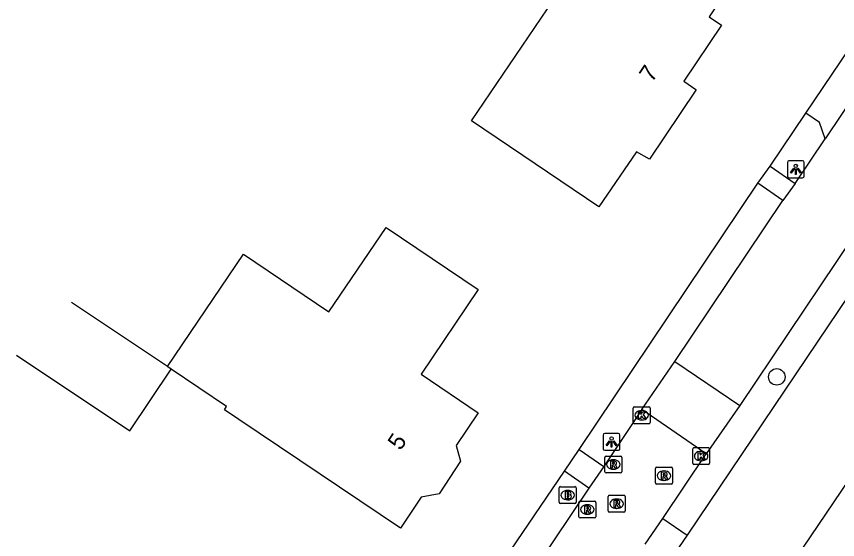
# Model space of a CAD drawing. Extents: x 163863 to 164644, y 379566 to 382155.
# Drawn here: x 164126.18 to 164174.78, y 381800.42 to 381831.4 of the extents above; entities that cross this region are included whole.
import ezdxf

# ---------------------------------------------------------------- set-up
doc = ezdxf.new("R2010")
doc.units = 0
for name, color, linetype in [('IMGEO_Boom', 7, 'Continuous'), ('IMGEO_Brandkraan', 7, 'Continuous'), ('IMGEO_Kolk', 7, 'Continuous'), ('IMGEO_Lichtpunt', 7, 'Continuous'), ('IMGEO_Pand', 7, 'Continuous'), ('IMGEO_Pand_nummerreeks', 7, 'Continuous'), ('IMGEO_Rijbaan_lokaal_open', 7, 'Continuous'), ('IMGEO_Rioolput', 7, 'Continuous'), ('IMGEO_Voetpad_halfverhard', 7, 'Continuous'), ('IMGEO_Voetpad_open', 7, 'Continuous')]:
    doc.layers.add(name, color=color, linetype=linetype)

msp = doc.modelspace()

# ---------------------------------------------------------------- linework, layer by layer
at = {"layer": 'IMGEO_Boom'}
msp.add_circle((164171.182, 381810.055), 0.489, dxfattribs=at)
at = {"layer": 'IMGEO_Brandkraan'}
for p, q in [((164158.31, 381802.628), (164158.31, 381803.48)), ((164158.385, 381803.554), (164159.237, 381803.554)), ((164158.798, 381803.334), (164158.823, 381803.334)), ((164159.311, 381803.48), (164159.311, 381802.628)), ((164159.237, 381802.554), (164158.385, 381802.554)), ((164158.821, 381802.774), (164158.796, 381802.774))]:
    msp.add_line(p, q, dxfattribs=at)
for points in [[(164158.31, 381802.628), (164158.31, 381803.48)], [(164158.385, 381803.554), (164159.237, 381803.554)], [(164159.311, 381803.48), (164159.311, 381802.628)], [(164158.658, 381803.254), (164158.658, 381802.854), (164158.871, 381802.854)], [(164158.889, 381803.254), (164158.658, 381803.254)], [(164158.837, 381803.173), (164158.783, 381803.173), (164158.783, 381803.097)], [(164158.783, 381803.097), (164158.836, 381803.097)], [(164158.845, 381803.021), (164158.783, 381803.021), (164158.783, 381802.94)], [(164158.783, 381802.94), (164158.845, 381802.94)], [(164159.237, 381802.554), (164158.385, 381802.554)]]:
    msp.add_lwpolyline(points, dxfattribs=at)
for centre, radius, start, end in [((164158.387, 381803.478), 0.0765, 91.552, 178.448), ((164158.387, 381803.478), 0.0765, 91.552, 178.448), ((164159.235, 381803.478), 0.0765, 1.552, 88.448), ((164159.235, 381803.478), 0.0765, 1.552, 88.448), ((164158.838, 381803.135), 0.0379, 267.8285, 90.9355), ((164158.846, 381802.98), 0.0404, 269.8759, 90.5077), ((164158.877, 381803.105), 0.251, 268.6676, 293.5347), ((164158.893, 381803.109), 0.145, 59.4692, 91.5367), ((164158.918, 381803.156), 0.0922, 285.5137, 58.1501), ((164158.923, 381802.964), 0.105, 301.3115, 78.989), ((164158.387, 381802.63), 0.0765, 181.552, 268.448), ((164158.387, 381802.63), 0.0765, 181.552, 268.448), ((164159.235, 381802.63), 0.0765, 271.552, 358.448), ((164159.235, 381802.63), 0.0765, 271.552, 358.448)]:
    msp.add_arc(centre, radius, start, end, dxfattribs=at)
for centre, major_axis, ratio, start_param, end_param in [((164158.797, 381803.054), (-0.387, 0.002), 0.722429, 4.712389, 7.853982), ((164158.822, 381803.054), (-0.39, 0.002), 0.717154, 1.570796, 4.712389)]:
    msp.add_ellipse(centre, major_axis=major_axis, ratio=ratio, start_param=start_param, end_param=end_param, dxfattribs=at)
at = {"layer": 'IMGEO_Kolk'}
for p, q in [((164162.687, 381807.358), (164162.687, 381808.21)), ((164162.762, 381808.284), (164163.614, 381808.284)), ((164163.688, 381808.21), (164163.688, 381807.358)), ((164163.175, 381808.064), (164163.2, 381808.064)), ((164163.614, 381807.284), (164162.762, 381807.284)), ((164163.198, 381807.504), (164163.173, 381807.504)), ((164166.206, 381804.939), (164166.206, 381805.791)), ((164166.281, 381805.865), (164167.133, 381805.865)), ((164167.207, 381805.791), (164167.207, 381804.939)), ((164166.694, 381805.645), (164166.719, 381805.645)), ((164167.133, 381804.865), (164166.281, 381804.865)), ((164166.717, 381805.085), (164166.692, 381805.085))]:
    msp.add_line(p, q, dxfattribs=at)
for points in [[(164162.687, 381807.358), (164162.687, 381808.21)], [(164162.762, 381808.284), (164163.614, 381808.284)], [(164163.688, 381808.21), (164163.688, 381807.358)], [(164163.008, 381807.984), (164163.131, 381807.984), (164163.131, 381807.833), (164163.261, 381807.984), (164163.425, 381807.984), (164163.279, 381807.833), (164163.432, 381807.584), (164163.28, 381807.584), (164163.195, 381807.748), (164163.131, 381807.681), (164163.131, 381807.584), (164163.008, 381807.584), (164163.008, 381807.984)], [(164163.614, 381807.284), (164162.762, 381807.284)], [(164166.206, 381804.939), (164166.206, 381805.791)], [(164166.281, 381805.865), (164167.133, 381805.865)], [(164167.207, 381805.791), (164167.207, 381804.939)], [(164166.527, 381805.565), (164166.65, 381805.565), (164166.65, 381805.414), (164166.78, 381805.565), (164166.944, 381805.565), (164166.798, 381805.414), (164166.951, 381805.165), (164166.799, 381805.165), (164166.714, 381805.329), (164166.65, 381805.262), (164166.65, 381805.165), (164166.527, 381805.165), (164166.527, 381805.565)], [(164167.133, 381804.865), (164166.281, 381804.865)]]:
    msp.add_lwpolyline(points, dxfattribs=at)
for centre, start, end in [((164162.764, 381808.208), 91.552, 178.448), ((164162.764, 381808.208), 91.552, 178.448), ((164163.612, 381808.208), 1.552, 88.448), ((164163.612, 381808.208), 1.552, 88.448), ((164162.764, 381807.36), 181.552, 268.448), ((164162.764, 381807.36), 181.552, 268.448), ((164163.612, 381807.36), 271.552, 358.448), ((164163.612, 381807.36), 271.552, 358.448), ((164166.283, 381805.789), 91.552, 178.448), ((164166.283, 381805.789), 91.552, 178.448), ((164167.131, 381805.789), 1.552, 88.448), ((164167.131, 381805.789), 1.552, 88.448), ((164166.283, 381804.941), 181.552, 268.448), ((164166.283, 381804.941), 181.552, 268.448), ((164167.131, 381804.941), 271.552, 358.448), ((164167.131, 381804.941), 271.552, 358.448)]:
    msp.add_arc(centre, 0.0765, start, end, dxfattribs=at)
for centre, major_axis, ratio, start_param, end_param in [((164163.174, 381807.784), (-0.387, 0.002), 0.722429, 4.712389, 7.853982), ((164163.199, 381807.784), (-0.39, 0.002), 0.717154, 1.570796, 4.712389), ((164166.693, 381805.365), (-0.387, 0.002), 0.722429, 4.712389, 7.853982), ((164166.718, 381805.365), (-0.39, 0.002), 0.717154, 1.570796, 4.712389)]:
    msp.add_ellipse(centre, major_axis=major_axis, ratio=ratio, start_param=start_param, end_param=end_param, dxfattribs=at)
at = {"layer": 'IMGEO_Lichtpunt'}
for p, q in [((164171.81, 381822.754), (164171.81, 381821.947)), ((164171.81, 381822.754), (164171.81, 381821.947)), ((164172.712, 381822.849), (164171.904, 381822.849)), ((164172.712, 381822.849), (164171.904, 381822.849)), ((164172.806, 381821.947), (164172.806, 381822.754)), ((164172.806, 381821.947), (164172.806, 381822.754)), ((164171.904, 381821.853), (164172.712, 381821.853)), ((164171.904, 381821.853), (164172.712, 381821.853)), ((164161.809, 381806.703), (164161.001, 381806.703)), ((164161.809, 381806.703), (164161.001, 381806.703)), ((164160.907, 381806.608), (164160.907, 381805.801)), ((164160.907, 381806.608), (164160.907, 381805.801)), ((164161.903, 381805.801), (164161.903, 381806.608)), ((164161.903, 381805.801), (164161.903, 381806.608)), ((164161.001, 381805.707), (164161.809, 381805.707)), ((164161.001, 381805.707), (164161.809, 381805.707))]:
    msp.add_line(p, q, dxfattribs=at)
for points in [[(164172.184, 381822.418), (164172.223, 381822.39), (164172.035, 381822.128), (164171.997, 381822.155), (164172.184, 381822.418)], [(164172.286, 381822.37), (164172.333, 381822.37), (164172.333, 381822.048), (164172.286, 381822.048), (164172.286, 381822.37)], [(164172.396, 381822.39), (164172.434, 381822.417), (164172.621, 381822.155), (164172.582, 381822.127), (164172.396, 381822.39)], [(164161.281, 381806.272), (164161.32, 381806.244), (164161.132, 381805.982), (164161.094, 381806.009), (164161.281, 381806.272)], [(164161.383, 381806.224), (164161.43, 381806.224), (164161.43, 381805.902), (164161.383, 381805.902), (164161.383, 381806.224)], [(164161.493, 381806.244), (164161.531, 381806.271), (164161.718, 381806.009), (164161.679, 381805.981), (164161.493, 381806.244)]]:
    msp.add_lwpolyline(points, dxfattribs=at)
for centre in [(164172.309, 381822.552), (164161.406, 381806.406)]:
    msp.add_circle(centre, 0.0994, dxfattribs=at)
for centre, start, end in [((164171.904, 381822.754), 90, 180), ((164171.904, 381822.754), 90, 180), ((164172.712, 381822.754), 0, 90), ((164172.712, 381822.754), 0, 90), ((164171.904, 381821.947), 180, 270), ((164171.904, 381821.947), 180, 270), ((164172.712, 381821.947), 270, 0), ((164172.712, 381821.947), 270, 360), ((164161.001, 381806.608), 90, 180), ((164161.001, 381806.608), 90, 180), ((164161.809, 381806.608), 0, 90), ((164161.809, 381806.608), 0, 90), ((164161.001, 381805.801), 180, 270), ((164161.001, 381805.801), 180, 270), ((164161.809, 381805.801), 270, 0), ((164161.809, 381805.801), 270, 360)]:
    msp.add_arc(centre, 0.0946, start, end, dxfattribs=at)
at = {"layer": 'IMGEO_Pand'}
for points in [[(164160.699, 381841.115), (164169.668, 381835.093), (164167.176, 381831.382), (164167.907, 381830.882), (164165.684, 381827.566), (164166.4, 381827.07), (164166.393, 381827.026), (164163.648, 381822.952), (164162.877, 381823.383), (164160.657, 381820.12), (164153.12, 381825.219), (164160.236, 381835.738), (164158.058, 381837.212), (164160.501, 381840.823)], [(164135.123, 381810.665), (164139.628, 381817.322), (164144.68, 381813.904), (164148.072, 381818.907), (164153.52, 381815.225), (164150.139, 381810.208), (164153.512, 381807.933), (164152.206, 381805.986), (164152.475, 381805.058), (164151.199, 381803.13), (164150.146, 381802.936), (164148.912, 381801.099), (164139.349, 381807.527), (164138.494, 381808.102), (164138.626, 381808.297), (164135.339, 381810.521)], [(164135.123, 381810.665), (164129.443, 381814.469)], [(164126.185, 381811.35), (164132.887, 381806.861), (164135.339, 381810.521)], [(164135.339, 381810.521), (164135.139, 381810.654), (164135.123, 381810.665)], [(164172.134, 381788.209), (164174.528, 381791.769), (164169.519, 381795.147), (164175.479, 381804.003), (164188.769, 381795.078), (164180.351, 381782.639), (164172.134, 381788.209)]]:
    msp.add_lwpolyline(points, dxfattribs=at)
at = {"layer": 'IMGEO_Rijbaan_lokaal_open'}
for points in [[(164172.905, 381825.67), (164176.013, 381830.292)], [(164183.294, 381829.671), (164168.994, 381808.366)], [(164177.875, 381829.852), (164174.051, 381824.163)], [(164174.051, 381824.163), (164173.716, 381825.119), (164172.905, 381825.67)], [(164172.275, 381821.514), (164174.051, 381824.163)], [(164172.275, 381821.514), (164171.541, 381820.495)], [(164165.146, 381810.963), (164171.541, 381820.495)], [(164163.204, 381808.122), (164165.146, 381810.963)], [(164165.146, 381810.963), (164168.994, 381808.366)], [(164168.994, 381808.366), (164167.007, 381805.504)], [(164163.204, 381808.122), (164160.947, 381804.756)], [(164167.007, 381805.504), (164163.204, 381808.122)], [(164164.432, 381801.664), (164167.007, 381805.504)], [(164160.947, 381804.756), (164160.068, 381803.456)], [(164160.068, 381803.456), (164155.87, 381797.223)], [(164163.391, 381800.153), (164164.432, 381801.664)]]:
    msp.add_lwpolyline(points, dxfattribs=at)
at = {"layer": 'IMGEO_Rioolput'}
for p, q in [((164161.009, 381804.438), (164161.009, 381805.29)), ((164161.084, 381805.364), (164161.936, 381805.364)), ((164162.01, 381805.29), (164162.01, 381804.438)), ((164161.497, 381805.144), (164161.522, 381805.144)), ((164161.936, 381804.364), (164161.084, 381804.364)), ((164161.52, 381804.584), (164161.495, 381804.584)), ((164164.005, 381803.778), (164164.005, 381804.63)), ((164164.08, 381804.704), (164164.932, 381804.704)), ((164164.493, 381804.484), (164164.518, 381804.484)), ((164165.006, 381804.63), (164165.006, 381803.778)), ((164164.516, 381803.924), (164164.491, 381803.924)), ((164164.932, 381803.704), (164164.08, 381803.704)), ((164161.205, 381802.117), (164161.205, 381802.969)), ((164161.28, 381803.043), (164162.132, 381803.043)), ((164161.693, 381802.823), (164161.718, 381802.823)), ((164162.206, 381802.969), (164162.206, 381802.117)), ((164159.474, 381801.774), (164159.474, 381802.626)), ((164159.549, 381802.7), (164160.401, 381802.7)), ((164159.962, 381802.48), (164159.987, 381802.48)), ((164160.475, 381802.626), (164160.475, 381801.774)), ((164159.985, 381801.92), (164159.96, 381801.92)), ((164162.132, 381802.043), (164161.28, 381802.043)), ((164161.716, 381802.263), (164161.691, 381802.263)), ((164160.401, 381801.7), (164159.549, 381801.7))]:
    msp.add_line(p, q, dxfattribs=at)
for points in [[(164161.009, 381804.438), (164161.009, 381805.29)], [(164161.084, 381805.364), (164161.936, 381805.364)], [(164162.01, 381805.29), (164162.01, 381804.438)], [(164161.598, 381805.062), (164161.346, 381805.064), (164161.346, 381804.664)], [(164161.346, 381804.664), (164161.47, 381804.664), (164161.47, 381804.826), (164161.481, 381804.826)], [(164161.524, 381804.983), (164161.47, 381804.983), (164161.47, 381804.902)], [(164161.47, 381804.902), (164161.522, 381804.902)], [(164161.528, 381804.797), (164161.599, 381804.664), (164161.739, 381804.664), (164161.674, 381804.79)], [(164161.936, 381804.364), (164161.084, 381804.364)], [(164164.005, 381803.778), (164164.005, 381804.63)], [(164164.08, 381804.704), (164164.932, 381804.704)], [(164164.594, 381804.402), (164164.342, 381804.404), (164164.342, 381804.004)], [(164164.52, 381804.323), (164164.466, 381804.323), (164164.466, 381804.242)], [(164165.006, 381804.63), (164165.006, 381803.778)], [(164164.342, 381804.004), (164164.466, 381804.004), (164164.466, 381804.166), (164164.477, 381804.166)], [(164164.466, 381804.242), (164164.518, 381804.242)], [(164164.524, 381804.137), (164164.595, 381804.004), (164164.735, 381804.004), (164164.67, 381804.13)], [(164164.932, 381803.704), (164164.08, 381803.704)], [(164161.205, 381802.117), (164161.205, 381802.969)], [(164161.28, 381803.043), (164162.132, 381803.043)], [(164162.206, 381802.969), (164162.206, 381802.117)], [(164159.474, 381801.774), (164159.474, 381802.626)], [(164159.549, 381802.7), (164160.401, 381802.7)], [(164160.063, 381802.398), (164159.811, 381802.4), (164159.811, 381802)], [(164160.475, 381802.626), (164160.475, 381801.774)], [(164161.794, 381802.741), (164161.542, 381802.743), (164161.542, 381802.343)], [(164161.542, 381802.343), (164161.666, 381802.343), (164161.666, 381802.505), (164161.677, 381802.505)], [(164161.72, 381802.662), (164161.666, 381802.662), (164161.666, 381802.581)], [(164161.666, 381802.581), (164161.718, 381802.581)], [(164161.724, 381802.476), (164161.795, 381802.343), (164161.935, 381802.343), (164161.87, 381802.469)], [(164159.811, 381802), (164159.935, 381802), (164159.935, 381802.162), (164159.946, 381802.162)], [(164159.989, 381802.319), (164159.935, 381802.319), (164159.935, 381802.238)], [(164159.935, 381802.238), (164159.987, 381802.238)], [(164159.993, 381802.133), (164160.064, 381802), (164160.204, 381802), (164160.139, 381802.126)], [(164162.132, 381802.043), (164161.28, 381802.043)], [(164160.401, 381801.7), (164159.549, 381801.7)]]:
    msp.add_lwpolyline(points, dxfattribs=at)
for centre, radius, start, end in [((164161.086, 381805.288), 0.0765, 91.552, 178.448), ((164161.086, 381805.288), 0.0765, 91.552, 178.448), ((164161.934, 381805.288), 0.0765, 1.552, 88.448), ((164161.934, 381805.288), 0.0765, 1.552, 88.448), ((164161.48, 381804.773), 0.0533, 26.0293, 88.6989), ((164161.506, 381805.091), 0.19, 274.7715, 282.9687), ((164161.53, 381804.887), 0.0964, 77.0061, 93.1865), ((164161.544, 381804.944), 0.0378, 276.6634, 79.6772), ((164161.597, 381804.952), 0.109, 350.3612, 89.416), ((164161.595, 381804.952), 0.112, 277.5842, 350.9817), ((164161.579, 381804.737), 0.108, 29.5134, 73.7905), ((164161.086, 381804.44), 0.0765, 181.552, 268.448), ((164161.086, 381804.44), 0.0765, 181.552, 268.448), ((164161.934, 381804.44), 0.0765, 271.552, 358.448), ((164161.934, 381804.44), 0.0765, 271.552, 358.448), ((164164.082, 381804.628), 0.0765, 91.552, 178.448), ((164164.082, 381804.628), 0.0765, 91.552, 178.448), ((164164.526, 381804.227), 0.0964, 77.0061, 93.1865), ((164164.54, 381804.284), 0.0378, 276.6634, 79.6772), ((164164.593, 381804.292), 0.109, 350.3612, 89.416), ((164164.591, 381804.292), 0.112, 277.5842, 350.9817), ((164164.93, 381804.628), 0.0765, 1.552, 88.448), ((164164.93, 381804.628), 0.0765, 1.552, 88.448), ((164164.476, 381804.113), 0.0533, 26.0293, 88.6989), ((164164.502, 381804.431), 0.19, 274.7715, 282.9687), ((164164.575, 381804.077), 0.108, 29.5134, 73.7905), ((164164.082, 381803.78), 0.0765, 181.552, 268.448), ((164164.082, 381803.78), 0.0765, 181.552, 268.448), ((164164.93, 381803.78), 0.0765, 271.552, 358.448), ((164164.93, 381803.78), 0.0765, 271.552, 358.448), ((164161.282, 381802.967), 0.0765, 91.552, 178.448), ((164161.282, 381802.967), 0.0765, 91.552, 178.448), ((164162.13, 381802.967), 0.0765, 1.552, 88.448), ((164162.13, 381802.967), 0.0765, 1.552, 88.448), ((164159.551, 381802.624), 0.0765, 91.552, 178.448), ((164159.551, 381802.624), 0.0765, 91.552, 178.448), ((164160.062, 381802.288), 0.109, 350.3612, 89.416), ((164160.399, 381802.624), 0.0765, 1.552, 88.448), ((164160.399, 381802.624), 0.0765, 1.552, 88.448), ((164161.676, 381802.452), 0.0533, 26.0293, 88.6989), ((164161.702, 381802.77), 0.19, 274.7715, 282.9687), ((164161.726, 381802.566), 0.0964, 77.0061, 93.1865), ((164161.74, 381802.623), 0.0378, 276.6634, 79.6772), ((164161.793, 381802.631), 0.109, 350.3612, 89.416), ((164161.791, 381802.631), 0.112, 277.5842, 350.9817), ((164161.775, 381802.416), 0.108, 29.5134, 73.7905), ((164159.945, 381802.109), 0.0533, 26.0293, 88.6989), ((164159.971, 381802.427), 0.19, 274.7715, 282.9687), ((164159.995, 381802.223), 0.0964, 77.0061, 93.1865), ((164160.009, 381802.28), 0.0378, 276.6634, 79.6772), ((164160.06, 381802.288), 0.112, 277.5842, 350.9817), ((164160.044, 381802.073), 0.108, 29.5134, 73.7905), ((164161.282, 381802.119), 0.0765, 181.552, 268.448), ((164161.282, 381802.119), 0.0765, 181.552, 268.448), ((164162.13, 381802.119), 0.0765, 271.552, 358.448), ((164162.13, 381802.119), 0.0765, 271.552, 358.448), ((164159.551, 381801.776), 0.0765, 181.552, 268.448), ((164159.551, 381801.776), 0.0765, 181.552, 268.448), ((164160.399, 381801.776), 0.0765, 271.552, 358.448), ((164160.399, 381801.776), 0.0765, 271.552, 358.448)]:
    msp.add_arc(centre, radius, start, end, dxfattribs=at)
for centre, major_axis, ratio, start_param, end_param in [((164161.496, 381804.864), (-0.387, 0.002), 0.722429, 4.712389, 7.853982), ((164161.521, 381804.864), (-0.39, 0.002), 0.717154, 1.570796, 4.712389), ((164164.492, 381804.204), (-0.387, 0.002), 0.722429, 4.712389, 7.853982), ((164164.517, 381804.204), (-0.39, 0.002), 0.717154, 1.570796, 4.712389), ((164161.692, 381802.543), (-0.387, 0.002), 0.722429, 4.712389, 7.853982), ((164161.717, 381802.543), (-0.39, 0.002), 0.717154, 1.570796, 4.712389), ((164159.961, 381802.2), (-0.387, 0.002), 0.722429, 4.712389, 7.853982), ((164159.986, 381802.2), (-0.39, 0.002), 0.717154, 1.570796, 4.712389)]:
    msp.add_ellipse(centre, major_axis=major_axis, ratio=ratio, start_param=start_param, end_param=end_param, dxfattribs=at)
at = {"layer": 'IMGEO_Voetpad_halfverhard'}
for points in [[(164185.088, 381829.228), (164165.885, 381800.687)], [(164170.786, 381822.53), (164172.905, 381825.67)], [(164159.489, 381805.76), (164170.069, 381821.522)], [(164154.029, 381797.699), (164158.614, 381804.471)]]:
    msp.add_lwpolyline(points, dxfattribs=at)
at = {"layer": 'IMGEO_Voetpad_open'}
for points in [[(164170.069, 381821.522), (164170.786, 381822.53)], [(164170.786, 381822.53), (164172.275, 381821.514)], [(164171.541, 381820.495), (164170.069, 381821.522)], [(164158.614, 381804.471), (164159.489, 381805.76)], [(164159.489, 381805.76), (164160.947, 381804.756)], [(164160.068, 381803.456), (164158.614, 381804.471)], [(164164.432, 381801.664), (164165.885, 381800.687)], [(164165.885, 381800.687), (164164.857, 381799.186)]]:
    msp.add_lwpolyline(points, dxfattribs=at)

# ---------------------------------------------------------------- texts
at = {"layer": 'IMGEO_Pand_nummerreeks'}
for s, rotation, p in [('7', 56.1613, (164163.8, 381827.449)), ('5', 56.4249, (164148.916, 381805.65))]:
    msp.add_text(s, height=1, rotation=rotation, dxfattribs=at).set_placement(p)

doc.saveas('drawing.dxf')
